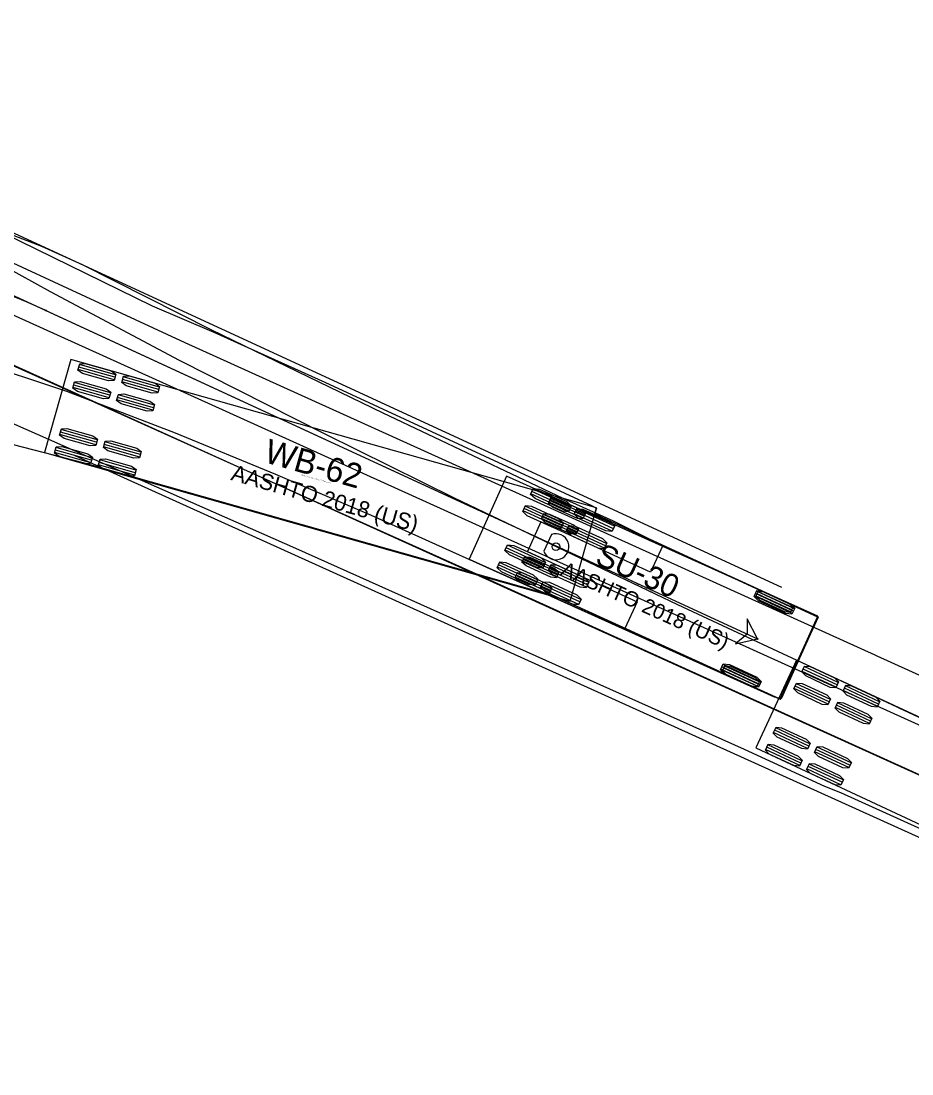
# Model space of a CAD drawing. Extents: x 186128 to 186702, y 352195 to 353183.
# Drawn here: x 186308.9 to 186387.2, y 352346 to 352438.5 of the extents above; entities that cross this region are included whole.
import ezdxf

# ---------------------------------------------------------------- set-up
doc = ezdxf.new("R2010")
doc.units = 0
doc.layers.add('SV_X_Control_Cells_Found', color=7, linetype='Continuous')
doc.layers.add('SV_X_Shot_Marker', color=7, linetype='Continuous')

msp = doc.modelspace()

# ---------------------------------------------------------------- linework, layer by layer
at = {"layer": 'SV_X_Control_Cells_Found'}
for p, q in [((186248.916, 352439.53), (186435.98, 352354.924)), ((186311.125, 352413.102), (186373.687, 352384.24)), ((186351.616, 352398.552), (186348.334, 352391.256)), ((186378.976, 352386.247), (186351.616, 352398.552)), ((186358.522, 352395.218), (186355.482, 352396.585)), ((186358.351, 352394.837), (186355.311, 352396.205)), ((186358.437, 352395.028), (186355.397, 352396.395)), ((186357.736, 352393.469), (186354.696, 352394.837)), ((186357.822, 352393.659), (186354.781, 352395.027)), ((186357.907, 352393.849), (186354.867, 352395.217)), ((186348.334, 352391.256), (186375.695, 352378.951)), ((186356.027, 352389.669), (186352.987, 352391.037)), ((186356.112, 352389.859), (186353.072, 352391.227)), ((186356.198, 352390.049), (186353.158, 352391.417)), ((186355.583, 352388.681), (186352.543, 352390.049)), ((186355.412, 352388.301), (186352.372, 352389.669)), ((186355.497, 352388.491), (186352.457, 352389.859)), ((186376.674, 352386.808), (186373.647, 352388.204)), ((186376.761, 352386.997), (186373.734, 352388.393)), ((186376.587, 352386.619), (186373.56, 352388.015)), ((186375.695, 352378.951), (186378.976, 352386.247)), ((186378.976, 352386.247), (186378.976, 352386.247)), ((186373.727, 352380.275), (186370.7, 352381.672)), ((186373.814, 352380.464), (186370.788, 352381.861)), ((186373.64, 352380.086), (186370.613, 352381.482))]:
    msp.add_line(p, q, dxfattribs=at)
for points in [[(186259.715, 352441.691), (186266.243, 352437.918), (186271.034, 352435.294), (186280.876, 352430.241), (186297.477, 352422.236), (186323.33, 352410.294), (186383.993, 352382.833)], [(186383.993, 352382.833), (186384.157, 352382.767), (186441.243, 352356.914), (186438.127, 352349.959), (186437.897, 352349.664), (186348.921, 352389.952), (186302.3, 352410.917), (186273.593, 352423.482), (186264.341, 352427.288), (186263.98, 352427.518), (186248.199, 352433.916), (186245.574, 352435.097), (186242.72, 352436.606), (186240.03, 352438.312), (186238.324, 352439.526)], [(186306.237, 352420.473), (186310.732, 352418.767), (186314.308, 352417.16), (186325.693, 352411.418), (186340.752, 352404.102), (186356.565, 352396.622), (186360.994, 352394.62), (186364.078, 352393.078), (186379.006, 352386.189), (186375.758, 352378.971), (186375.168, 352379.135), (186339.735, 352395.08), (186331.336, 352398.689), (186322.51, 352402.33), (186312.963, 352405.972), (186304.826, 352408.695)], [(186358.543, 352395.265), (186358.33, 352394.79), (186357.84, 352394.839), (186355.651, 352395.823), (186355.29, 352396.158), (186355.503, 352396.632), (186355.993, 352396.583), (186358.182, 352395.599), (186358.543, 352395.265)], [(186357.928, 352393.897), (186357.715, 352393.422), (186357.225, 352393.471), (186355.036, 352394.455), (186354.675, 352394.79), (186354.888, 352395.264), (186355.378, 352395.215), (186357.567, 352394.231), (186357.928, 352393.897)], [(186356.219, 352390.097), (186356.006, 352389.622), (186355.516, 352389.671), (186353.327, 352390.655), (186352.966, 352390.99), (186353.179, 352391.464), (186353.669, 352391.415), (186355.858, 352390.431), (186356.219, 352390.097)], [(186355.604, 352388.729), (186355.391, 352388.254), (186354.901, 352388.303), (186352.712, 352389.287), (186352.351, 352389.622), (186352.564, 352390.096), (186353.054, 352390.047), (186355.243, 352389.063), (186355.604, 352388.729)], [(186376.783, 352387.044), (186376.565, 352386.572), (186376.076, 352386.625), (186373.896, 352387.63), (186373.538, 352387.968), (186373.756, 352388.44), (186374.245, 352388.387), (186376.425, 352387.382), (186376.783, 352387.044)], [(186373.687, 352384.24), (186372.756, 352386.01), (186372.779, 352384.659), (186371.736, 352383.799), (186373.687, 352384.24)], [(186373.836, 352380.511), (186373.618, 352380.039), (186373.129, 352380.092), (186370.95, 352381.098), (186370.591, 352381.435), (186370.809, 352381.908), (186371.299, 352381.854), (186373.478, 352380.849), (186373.836, 352380.511)]]:
    msp.add_lwpolyline(points, dxfattribs=at)
msp.add_lwpolyline([(186373.687, 352384.24), (186372.756, 352386.01), (186372.779, 352384.659), (186371.736, 352383.799)], close=True, dxfattribs=at)
for centre in [(186311.125, 352413.102), (186311.125, 352413.102), (186373.687, 352384.24)]:
    msp.add_circle(centre, 0.0417, dxfattribs=at)
msp.add_arc((186281.801, 352349.54), 70, 65.23429, 154.68306, dxfattribs=at)
at = {"layer": 'SV_X_Shot_Marker'}
for p, q in [((186269.985, 352437.588), (186375.782, 352388.78)), ((186285.943, 352424.719), (186373.687, 352384.24)), ((186292.856, 352415.266), (186434.331, 352351.279)), ((186313.322, 352408.808), (186311.011, 352400.628)), ((186359.514, 352395.757), (186313.322, 352408.808)), ((186317.129, 352407.018), (186313.953, 352407.916)), ((186317.191, 352407.239), (186314.015, 352408.136)), ((186317.253, 352407.459), (186314.078, 352408.357)), ((186316.805, 352405.871), (186313.629, 352406.769)), ((186320.978, 352405.931), (186317.802, 352406.828)), ((186321.04, 352406.151), (186317.865, 352407.048)), ((186321.103, 352406.372), (186317.927, 352407.269)), ((186316.68, 352405.43), (186313.505, 352406.328)), ((186316.743, 352405.651), (186313.567, 352406.548)), ((186320.53, 352404.343), (186317.354, 352405.24)), ((186320.592, 352404.563), (186317.416, 352405.461)), ((186320.654, 352404.784), (186317.478, 352405.681)), ((186315.516, 352401.308), (186312.34, 352402.206)), ((186315.578, 352401.529), (186312.402, 352402.426)), ((186315.64, 352401.75), (186312.465, 352402.647)), ((186319.365, 352400.221), (186316.189, 352401.118)), ((186319.427, 352400.441), (186316.252, 352401.339)), ((186319.49, 352400.662), (186316.314, 352401.559)), ((186311.011, 352400.628), (186357.203, 352387.577)), ((186315.067, 352399.721), (186311.891, 352400.618)), ((186315.129, 352399.941), (186311.954, 352400.838)), ((186315.192, 352400.162), (186312.016, 352401.059)), ((186313.666, 352400.367), (186432.271, 352346.724)), ((186318.916, 352398.633), (186315.741, 352399.53)), ((186318.979, 352398.854), (186315.803, 352399.751)), ((186319.041, 352399.074), (186315.865, 352399.971)), ((186357.278, 352395.887), (186353.943, 352397.412)), ((186357.087, 352395.47), (186353.752, 352396.995)), ((186357.182, 352395.679), (186353.848, 352397.203)), ((186356.496, 352394.178), (186353.162, 352395.703)), ((186356.592, 352394.387), (186353.257, 352395.911)), ((186357.203, 352387.577), (186359.514, 352395.757)), ((186361.097, 352394.141), (186357.763, 352395.666)), ((186359.514, 352395.757), (186359.514, 352395.757)), ((186356.401, 352393.97), (186353.066, 352395.494)), ((186360.907, 352393.724), (186357.572, 352395.249)), ((186361.002, 352393.933), (186357.667, 352395.457)), ((186354.638, 352394.524), (186353.447, 352391.916)), ((186364.279, 352390.117), (186354.638, 352394.524)), ((186360.221, 352392.224), (186356.886, 352393.748)), ((186360.316, 352392.432), (186356.981, 352393.957)), ((186360.411, 352392.641), (186357.077, 352394.165)), ((186355.553, 352393.418), (186354.881, 352391.948)), ((186354.828, 352390.529), (186351.493, 352392.053)), ((186354.923, 352390.737), (186351.589, 352392.262)), ((186355.019, 352390.946), (186351.684, 352392.47)), ((186353.447, 352391.916), (186363.087, 352387.509)), ((186365.346, 352392.451), (186364.279, 352390.117)), ((186378.988, 352386.215), (186365.346, 352392.451)), ((186354.333, 352389.445), (186350.998, 352390.97)), ((186354.142, 352389.028), (186350.807, 352390.553)), ((186354.237, 352389.237), (186350.903, 352390.761)), ((186358.648, 352388.783), (186355.313, 352390.307)), ((186358.743, 352388.991), (186355.408, 352390.516)), ((186358.838, 352389.2), (186355.504, 352390.724)), ((186358.152, 352387.699), (186354.818, 352389.223)), ((186357.962, 352387.282), (186354.627, 352388.807)), ((186358.057, 352387.491), (186354.722, 352389.015)), ((186376.826, 352386.692), (186373.496, 352388.228)), ((186376.922, 352386.9), (186373.592, 352388.436)), ((186363.087, 352387.509), (186362.02, 352385.175)), ((186376.73, 352386.484), (186373.4, 352388.02)), ((186375.662, 352378.939), (186378.988, 352386.215)), ((186378.988, 352386.215), (186378.988, 352386.215)), ((186362.02, 352385.175), (186375.662, 352378.939)), ((186373.878, 352380.251), (186370.549, 352381.787)), ((186373.974, 352380.459), (186370.645, 352381.995)), ((186377.111, 352382.376), (186373.523, 352374.67)), ((186420.625, 352362.112), (186377.111, 352382.376)), ((186380.777, 352380.416), (186377.785, 352381.809)), ((186373.782, 352380.043), (186370.453, 352381.579)), ((186380.583, 352380), (186377.592, 352381.394)), ((186380.68, 352380.208), (186377.688, 352381.601)), ((186379.887, 352378.505), (186376.895, 352379.898)), ((186379.983, 352378.712), (186376.992, 352380.106)), ((186380.08, 352378.92), (186377.089, 352380.313)), ((186384.306, 352378.52), (186381.315, 352379.913)), ((186384.403, 352378.727), (186381.411, 352380.12)), ((186384.209, 352378.312), (186381.218, 352379.705)), ((186383.513, 352376.816), (186380.521, 352378.209)), ((186383.61, 352377.024), (186380.618, 352378.417)), ((186383.706, 352377.232), (186380.715, 352378.625)), ((186378.175, 352374.829), (186375.184, 352376.223)), ((186378.272, 352375.037), (186375.28, 352376.43)), ((186378.078, 352374.622), (186375.087, 352376.015)), ((186373.523, 352374.67), (186417.036, 352354.407)), ((186377.382, 352373.126), (186374.39, 352374.519)), ((186377.479, 352373.334), (186374.487, 352374.727)), ((186377.575, 352373.541), (186374.584, 352374.935)), ((186381.705, 352372.933), (186378.713, 352374.326)), ((186381.801, 352373.141), (186378.81, 352374.534)), ((186381.898, 352373.349), (186378.907, 352374.742)), ((186381.008, 352371.437), (186378.016, 352372.83)), ((186381.105, 352371.645), (186378.113, 352373.038)), ((186381.201, 352371.853), (186378.21, 352373.246))]:
    msp.add_line(p, q, dxfattribs=at)
for points in [[(186271.556, 352440.212), (186274.444, 352437.981), (186281.432, 352432.961), (186288.715, 352428.106), (186297.377, 352422.791), (186304.595, 352418.591), (186311.484, 352414.785), (186322.836, 352408.749), (186335.631, 352402.253), (186347.016, 352396.642), (186366.635, 352387.259), (186385.927, 352378.27)], [(186307.379, 352419.922), (186320.469, 352413.524), (186325.882, 352411.195), (186335.627, 352406.798), (186359.085, 352395.972), (186359.511, 352395.742), (186359.38, 352395.283), (186359.938, 352394.987), (186378.999, 352386.162), (186375.85, 352379.272), (186375.62, 352378.977), (186355.837, 352387.999), (186314.4, 352399.712), (186305.64, 352401.976)], [(186317.269, 352407.514), (186317.113, 352406.964), (186316.622, 352406.923), (186314.335, 352407.569), (186313.938, 352407.861), (186314.093, 352408.411), (186314.585, 352408.451), (186316.871, 352407.805), (186317.269, 352407.514)], [(186316.82, 352405.926), (186316.665, 352405.376), (186316.173, 352405.335), (186313.887, 352405.982), (186313.489, 352406.273), (186313.645, 352406.823), (186314.136, 352406.864), (186316.423, 352406.218), (186316.82, 352405.926)], [(186321.118, 352406.426), (186320.963, 352405.876), (186320.471, 352405.836), (186318.185, 352406.482), (186317.787, 352406.773), (186317.943, 352407.324), (186318.434, 352407.364), (186320.72, 352406.718), (186321.118, 352406.426)], [(186320.67, 352404.839), (186320.514, 352404.288), (186320.023, 352404.248), (186317.736, 352404.894), (186317.338, 352405.185), (186317.494, 352405.736), (186317.985, 352405.776), (186320.272, 352405.13), (186320.67, 352404.839)], [(186385.927, 352378.27), (186386.091, 352378.204), (186420.441, 352362.226), (186420.638, 352362.128), (186420.539, 352361.898), (186420.802, 352361.767), (186439.634, 352353.27), (186436.517, 352346.314), (186436.353, 352346.019), (186436.189, 352346.052), (186417.423, 352354.582), (186417.193, 352354.648), (186417.062, 352354.418), (186416.209, 352354.779), (186381.005, 352370.724), (186379.595, 352371.282), (186372.541, 352374.53), (186333.105, 352392.181), (186307.383, 352403.532)], [(186315.656, 352401.804), (186315.5, 352401.254), (186315.009, 352401.214), (186312.722, 352401.86), (186312.324, 352402.151), (186312.48, 352402.701), (186312.971, 352402.742), (186315.258, 352402.096), (186315.656, 352401.804)], [(186315.207, 352400.216), (186315.051, 352399.666), (186314.56, 352399.626), (186312.274, 352400.272), (186311.876, 352400.563), (186312.031, 352401.114), (186312.523, 352401.154), (186314.809, 352400.508), (186315.207, 352400.216)], [(186319.505, 352400.717), (186319.349, 352400.166), (186318.858, 352400.126), (186316.571, 352400.772), (186316.174, 352401.063), (186316.329, 352401.614), (186316.821, 352401.654), (186319.107, 352401.008), (186319.505, 352400.717)], [(186319.056, 352399.129), (186318.901, 352398.578), (186318.409, 352398.538), (186316.123, 352399.184), (186315.725, 352399.476), (186315.881, 352400.026), (186316.372, 352400.066), (186318.659, 352399.42), (186319.056, 352399.129)], [(186357.301, 352395.939), (186357.063, 352395.419), (186356.525, 352395.475), (186354.124, 352396.573), (186353.729, 352396.943), (186353.966, 352397.463), (186354.505, 352397.407), (186356.906, 352396.309), (186357.301, 352395.939)], [(186356.615, 352394.438), (186356.377, 352393.918), (186355.839, 352393.975), (186353.438, 352395.072), (186353.043, 352395.443), (186353.28, 352395.963), (186353.819, 352395.906), (186356.22, 352394.809), (186356.615, 352394.438)], [(186361.121, 352394.193), (186360.883, 352393.673), (186360.345, 352393.729), (186357.944, 352394.827), (186357.548, 352395.197), (186357.786, 352395.717), (186358.325, 352395.661), (186360.726, 352394.563), (186361.121, 352394.193)], [(186360.435, 352392.692), (186360.197, 352392.172), (186359.659, 352392.229), (186357.258, 352393.326), (186356.862, 352393.696), (186357.1, 352394.217), (186357.639, 352394.16), (186360.04, 352393.062), (186360.435, 352392.692)], [(186355.042, 352390.998), (186354.804, 352390.477), (186354.266, 352390.534), (186351.865, 352391.632), (186351.47, 352392.002), (186351.708, 352392.522), (186352.246, 352392.465), (186354.647, 352391.368), (186355.042, 352390.998)], [(186354.356, 352389.497), (186354.118, 352388.977), (186353.58, 352389.033), (186351.179, 352390.131), (186350.784, 352390.501), (186351.022, 352391.021), (186351.56, 352390.965), (186353.961, 352389.867), (186354.356, 352389.497)], [(186358.862, 352389.251), (186358.624, 352388.731), (186358.086, 352388.788), (186355.685, 352389.885), (186355.29, 352390.256), (186355.527, 352390.776), (186356.066, 352390.719), (186358.467, 352389.621), (186358.862, 352389.251)], [(186358.176, 352387.751), (186357.938, 352387.23), (186357.4, 352387.287), (186354.999, 352388.385), (186354.604, 352388.755), (186354.841, 352389.275), (186355.38, 352389.218), (186357.781, 352388.121), (186358.176, 352387.751)], [(186376.946, 352386.952), (186376.706, 352386.432), (186376.168, 352386.491), (186373.77, 352387.597), (186373.377, 352387.968), (186373.616, 352388.488), (186374.154, 352388.429), (186376.552, 352387.323), (186376.946, 352386.952)], [(186373.687, 352384.24), (186372.756, 352386.01), (186372.779, 352384.659), (186371.736, 352383.799), (186373.687, 352384.24)], [(186373.998, 352380.511), (186373.758, 352379.992), (186373.22, 352380.05), (186370.823, 352381.156), (186370.429, 352381.528), (186370.668, 352382.047), (186371.207, 352381.988), (186373.604, 352380.883), (186373.998, 352380.511)], [(186380.801, 352380.467), (186380.559, 352379.949), (186380.068, 352379.988), (186377.914, 352380.991), (186377.568, 352381.342), (186377.809, 352381.861), (186378.301, 352381.822), (186380.455, 352380.819), (186380.801, 352380.467)], [(186380.104, 352378.972), (186379.863, 352378.453), (186379.371, 352378.492), (186377.217, 352379.495), (186376.871, 352379.846), (186377.113, 352380.365), (186377.604, 352380.326), (186379.758, 352379.323), (186380.104, 352378.972)], [(186384.427, 352378.779), (186384.185, 352378.26), (186383.694, 352378.299), (186381.54, 352379.302), (186381.194, 352379.653), (186381.435, 352380.172), (186381.927, 352380.133), (186384.081, 352379.13), (186384.427, 352378.779)], [(186383.73, 352377.283), (186383.489, 352376.765), (186382.997, 352376.803), (186380.843, 352377.806), (186380.497, 352378.158), (186380.739, 352378.676), (186381.23, 352378.637), (186383.384, 352377.634), (186383.73, 352377.283)], [(186378.296, 352375.089), (186378.054, 352374.57), (186377.563, 352374.609), (186375.409, 352375.612), (186375.063, 352375.963), (186375.304, 352376.482), (186375.796, 352376.443), (186377.95, 352375.44), (186378.296, 352375.089)], [(186377.599, 352373.593), (186377.358, 352373.074), (186376.866, 352373.113), (186374.712, 352374.116), (186374.366, 352374.468), (186374.608, 352374.986), (186375.099, 352374.947), (186377.253, 352373.944), (186377.599, 352373.593)], [(186381.922, 352373.4), (186381.681, 352372.882), (186381.189, 352372.92), (186379.035, 352373.923), (186378.689, 352374.275), (186378.93, 352374.793), (186379.422, 352374.754), (186381.576, 352373.751), (186381.922, 352373.4)], [(186381.225, 352371.904), (186380.984, 352371.386), (186380.492, 352371.425), (186378.339, 352372.428), (186377.992, 352372.779), (186378.234, 352373.297), (186378.726, 352373.259), (186380.879, 352372.256), (186381.225, 352371.904)]]:
    msp.add_lwpolyline(points, dxfattribs=at)
msp.add_lwpolyline([(186373.687, 352384.24), (186372.756, 352386.01), (186372.779, 352384.659), (186371.736, 352383.799)], close=True, dxfattribs=at)
for centre, radius in [((186355.952, 352392.347), 0.34), ((186373.687, 352384.24), 0.0417)]:
    msp.add_circle(centre, radius, dxfattribs=at)
msp.add_arc((186355.952, 352392.347), 1.143, 200.43297, 110.43297, dxfattribs=at)

# ---------------------------------------------------------------- texts
at = {"layer": 'SV_X_Control_Cells_Found'}
for s, height, p in [('SU-30', 2, (186359.291, 352390.89)), ('AASHTO 2018 (US)', 1.33333, (186356.252, 352389.881)), ('(c) 2025 Transoft Solutions, Inc. All rights reserved.', 0.08, (186362.145, 352389.387))]:
    msp.add_text(s, height=height, rotation=335.78453, dxfattribs=at).set_placement(p)
at = {"layer": 'SV_X_Shot_Marker'}
for s, height, p in [('WB-62', 2.125, (186330.196, 352399.801)), ('AASHTO 2018 (US)', 1.41667, (186327.306, 352398.225)), ('(c) 2025 Transoft Solutions, Inc. All rights reserved.', 0.085, (186333.576, 352398.625))]:
    msp.add_text(s, height=height, rotation=344.22274, dxfattribs=at).set_placement(p)

doc.saveas('drawing.dxf')
